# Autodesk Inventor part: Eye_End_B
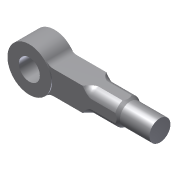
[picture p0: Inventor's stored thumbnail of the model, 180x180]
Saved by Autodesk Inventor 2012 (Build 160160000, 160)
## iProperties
Created: 2011-09
Part Number: Eye_End_B
Material: Default
Document SubType Name: Modeling
Designer: CADCIM
Density: 1 g/cm^3
Author: CADCIM
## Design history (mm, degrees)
sketch "Sketch1"
  geometry: 1 further point
sketch "Sketch2"
  geometry: L1 (0, 0)-(-112.462, 0); L2 (-21.909, 14)-(-105, 14); L3 (-105, 14)-(-105, -14); L4 (-105, -14)-(-21.909, -14); C1 r 12.5 at (0, 0); A1 r 26 centre (0, 0) between (-21.909, -14) and (-21.909, 14); 1 further point
  constraints: 8 end point, 2 centre point, 2 coincident, 2 parallel, 2 point on circle, 1 horizontal, 1 perpendicular, 1 other
  dimensions: "d0" = 25 diameter of C1; "d1" = 52 diameter of A1; "d2" = 28 distance between parallel lines of L4 L2; "d3" = 105 distance from line of L3 point (0, 0)
extrude "Extrusion1" new body sketch "Sketch2" stored distance "d4" = 28; taper "d5" = 0 deg
sketch "Sketch3"
  geometry: C1 r 12.5 at (0, 0) reference; C2 r 26 at (0, 0); C3 r 12.5 at (0, 0); A1 r 26 centre (0, 0) between (21.909, 14) and (21.909, -14) reference
  constraints: 2 centre point, 2 coincident, 2 concentric
extrude "Extrusion2" join sketch "Sketch3" distance "d6" = 1; taper "d7" = 0 deg
mirror "Mirror1"
sketch "Sketch4"
  geometry: C1 r 12.5 at (14, 14); 1 further point
  constraints: 1 centre point, 1 coincident
  dimensions: "d8" = 25 diameter of C1
extrude "Extrusion3" join sketch "Sketch4" distance "d9" = 35; taper "d10" = 0 deg
sketch "Sketch5"
  geometry: L1 (-105, 14)-(-21.909, 14) reference; L2 (-105, -14)-(-105, 14) reference; L3 (-105, 15)-(-72.799, 15); L4 (-62.899, 19.101)-(-61, 21); L5 (-61, 21)-(-105, 21); L6 (-105, 21)-(-105, 15); L7 (0, 0)-(-163.801, 0); A1 r 14 centre (-72.799, 29) between (-72.799, 15) and (-62.899, 19.101)
  constraints: 10 end point, 3 perpendicular, 2 point on circle, 2 tangent, 1 centre point, 1 collinear, 1 parallel
  dimensions: "d16" = 44 distance of L4.end L5.end; "d17" = 135 deg angle of L3 L4; "d18" = 14 radius of A1; "d19" = 1 distance between parallel lines of L1 L3; "d20" = 6 distance of L5.end L3.start
revolve "Revolution1" sketch "Sketch5" stored, may be unused: angle "d21" = 90 deg
sketch "Sketch6"
  geometry: C1 r 12.5 at (14, 5.385) reference; C2 r 12.5 at (14, 5.385); C3 r 17.5 at (14, 5.385); A1 r 15 centre (14, 5.385) between (19.385, -8.615) and (28, 0) reference
  constraints: 2 centre point, 2 coincident, 1 concentric
  dimensions: "d22" = 35 diameter of C3
extrude "Extrusion4" cut sketch "Sketch6" distance "d23" = 5; taper "d24" = -32 deg
fillet "Fillet1" dims "d25" = 12
body "Solid1"
